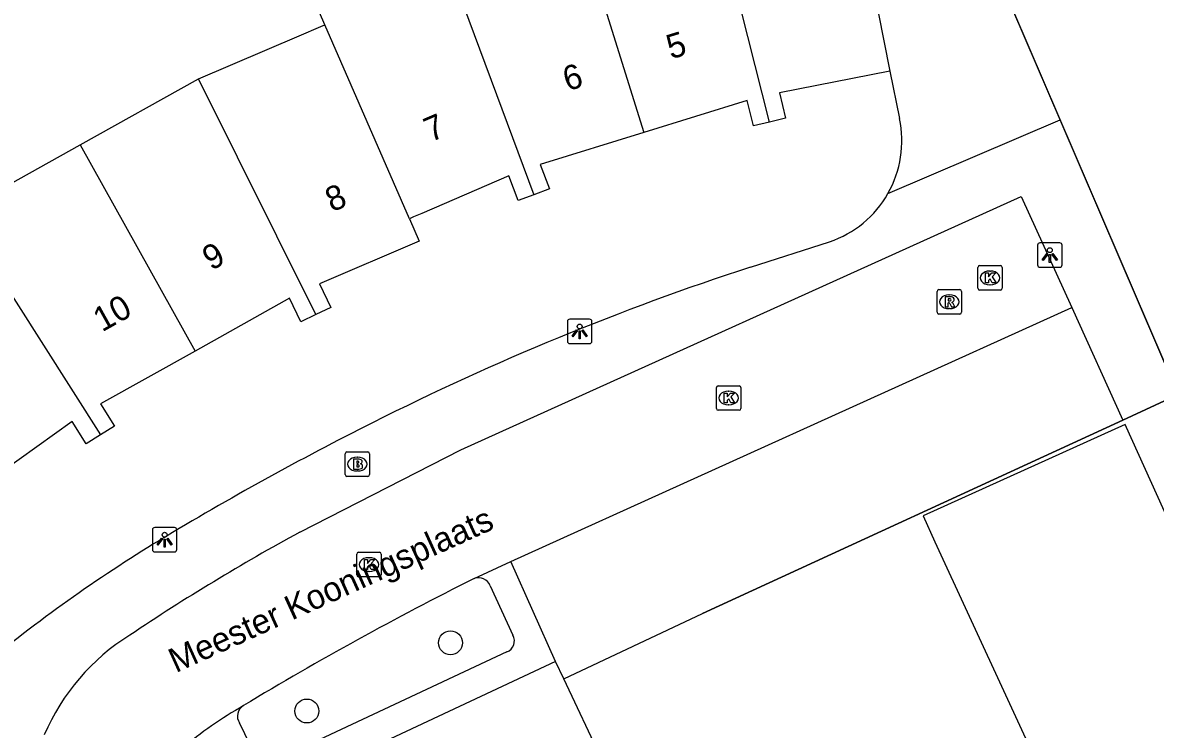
# Model space of a CAD drawing. Extents: x 160379 to 161131, y 383940 to 384849.
# Drawn here: x 160925.77 to 160972.04, y 384329.72 to 384358.59 of the extents above; entities that cross this region are included whole.
import ezdxf

# ---------------------------------------------------------------- set-up
doc = ezdxf.new("R2010")
doc.units = 0
for name, color, linetype in [('IMGEO_Boom', 7, 'Continuous'), ('IMGEO_Brandkraan', 7, 'Continuous'), ('IMGEO_Kolk', 7, 'Continuous'), ('IMGEO_Lichtpunt', 7, 'Continuous'), ('IMGEO_Muur', 7, 'Continuous'), ('IMGEO_Openbare_ruimte_label', 7, 'Continuous'), ('IMGEO_Pand', 7, 'Continuous'), ('IMGEO_Pand_nummerreeks', 7, 'Continuous'), ('IMGEO_Parkeervlak_open', 7, 'Continuous'), ('IMGEO_Rijbaan_lokaal_open', 7, 'Continuous'), ('IMGEO_Rioolput', 7, 'Continuous'), ('IMGEO_Voetpad_open', 7, 'Continuous')]:
    doc.layers.add(name, color=color, linetype=linetype)

msp = doc.modelspace()

# ---------------------------------------------------------------- linework, layer by layer
at = {"layer": 'IMGEO_Boom'}
for centre in [(160943.246, 384333.257), (160937.378, 384330.47)]:
    msp.add_circle(centre, 0.489, dxfattribs=at)
at = {"layer": 'IMGEO_Brandkraan'}
for p, q in [((160938.941, 384340.129), (160938.941, 384340.981)), ((160939.016, 384341.055), (160939.868, 384341.055)), ((160939.429, 384340.835), (160939.454, 384340.835)), ((160939.942, 384340.981), (160939.942, 384340.129)), ((160939.452, 384340.275), (160939.427, 384340.275)), ((160939.868, 384340.055), (160939.016, 384340.055))]:
    msp.add_line(p, q, dxfattribs=at)
for points in [[(160938.941, 384340.129), (160938.941, 384340.981)], [(160939.016, 384341.055), (160939.868, 384341.055)], [(160939.289, 384340.755), (160939.289, 384340.355), (160939.502, 384340.355)], [(160939.52, 384340.755), (160939.289, 384340.755)], [(160939.468, 384340.674), (160939.414, 384340.674), (160939.414, 384340.598)], [(160939.942, 384340.981), (160939.942, 384340.129)], [(160939.414, 384340.598), (160939.467, 384340.598)], [(160939.476, 384340.522), (160939.414, 384340.522), (160939.414, 384340.441)], [(160939.414, 384340.441), (160939.476, 384340.441)], [(160939.868, 384340.055), (160939.016, 384340.055)]]:
    msp.add_lwpolyline(points, dxfattribs=at)
for centre, radius, start, end in [((160939.018, 384340.979), 0.0765, 91.552, 178.448), ((160939.018, 384340.979), 0.0765, 91.552, 178.448), ((160939.469, 384340.636), 0.0379, 267.8285, 90.9355), ((160939.524, 384340.61), 0.145, 59.4692, 91.5367), ((160939.549, 384340.657), 0.0922, 285.5137, 58.1501), ((160939.866, 384340.979), 0.0765, 1.552, 88.448), ((160939.866, 384340.979), 0.0765, 1.552, 88.448), ((160939.477, 384340.481), 0.0404, 269.8759, 90.5077), ((160939.508, 384340.606), 0.251, 268.6676, 293.5347), ((160939.554, 384340.465), 0.105, 301.3115, 78.989), ((160939.018, 384340.131), 0.0765, 181.552, 268.448), ((160939.018, 384340.131), 0.0765, 181.552, 268.448), ((160939.866, 384340.131), 0.0765, 271.552, 358.448), ((160939.866, 384340.131), 0.0765, 271.552, 358.448)]:
    msp.add_arc(centre, radius, start, end, dxfattribs=at)
for centre, major_axis, ratio, start_param, end_param in [((160939.428, 384340.555), (-0.387, 0.002), 0.722429, 4.712389, 7.853982), ((160939.453, 384340.555), (-0.39, 0.002), 0.717154, 1.570796, 4.712389)]:
    msp.add_ellipse(centre, major_axis=major_axis, ratio=ratio, start_param=start_param, end_param=end_param, dxfattribs=at)
at = {"layer": 'IMGEO_Kolk'}
for p, q in [((160964.784, 384347.737), (160964.784, 384348.589)), ((160964.859, 384348.663), (160965.711, 384348.663)), ((160965.785, 384348.589), (160965.785, 384347.737)), ((160965.272, 384348.443), (160965.297, 384348.443)), ((160965.711, 384347.663), (160964.859, 384347.663)), ((160965.295, 384347.883), (160965.27, 384347.883)), ((160954.106, 384342.829), (160954.106, 384343.681)), ((160954.181, 384343.755), (160955.033, 384343.755)), ((160954.594, 384343.535), (160954.619, 384343.535)), ((160955.107, 384343.681), (160955.107, 384342.829)), ((160954.617, 384342.975), (160954.592, 384342.975)), ((160955.033, 384342.755), (160954.181, 384342.755)), ((160939.491, 384336.953), (160940.343, 384336.953)), ((160939.416, 384336.027), (160939.416, 384336.879)), ((160939.904, 384336.733), (160939.929, 384336.733)), ((160940.417, 384336.879), (160940.417, 384336.027)), ((160939.927, 384336.173), (160939.902, 384336.173)), ((160940.343, 384335.953), (160939.491, 384335.953))]:
    msp.add_line(p, q, dxfattribs=at)
for points in [[(160964.784, 384347.737), (160964.784, 384348.589)], [(160964.859, 384348.663), (160965.711, 384348.663)], [(160965.785, 384348.589), (160965.785, 384347.737)], [(160965.105, 384348.363), (160965.228, 384348.363), (160965.228, 384348.212), (160965.358, 384348.363), (160965.522, 384348.363), (160965.376, 384348.212), (160965.529, 384347.963), (160965.377, 384347.963), (160965.292, 384348.127), (160965.228, 384348.06), (160965.228, 384347.963), (160965.105, 384347.963), (160965.105, 384348.363)], [(160965.711, 384347.663), (160964.859, 384347.663)], [(160954.106, 384342.829), (160954.106, 384343.681)], [(160954.181, 384343.755), (160955.033, 384343.755)], [(160954.427, 384343.455), (160954.55, 384343.455), (160954.55, 384343.304), (160954.68, 384343.455), (160954.844, 384343.455), (160954.698, 384343.304), (160954.851, 384343.055), (160954.699, 384343.055), (160954.614, 384343.219), (160954.55, 384343.152), (160954.55, 384343.055), (160954.427, 384343.055), (160954.427, 384343.455)], [(160955.107, 384343.681), (160955.107, 384342.829)], [(160955.033, 384342.755), (160954.181, 384342.755)], [(160939.491, 384336.953), (160940.343, 384336.953)], [(160939.416, 384336.027), (160939.416, 384336.879)], [(160939.737, 384336.653), (160939.86, 384336.653), (160939.86, 384336.502), (160939.99, 384336.653), (160940.154, 384336.653), (160940.008, 384336.502), (160940.161, 384336.253), (160940.009, 384336.253), (160939.924, 384336.417), (160939.86, 384336.35), (160939.86, 384336.253), (160939.737, 384336.253), (160939.737, 384336.653)], [(160940.417, 384336.879), (160940.417, 384336.027)], [(160940.343, 384335.953), (160939.491, 384335.953)]]:
    msp.add_lwpolyline(points, dxfattribs=at)
for centre, start, end in [((160964.861, 384348.587), 91.552, 178.448), ((160964.861, 384348.587), 91.552, 178.448), ((160965.709, 384348.587), 1.552, 88.448), ((160965.709, 384348.587), 1.552, 88.448), ((160964.861, 384347.739), 181.552, 268.448), ((160964.861, 384347.739), 181.552, 268.448), ((160965.709, 384347.739), 271.552, 358.448), ((160965.709, 384347.739), 271.552, 358.448), ((160954.183, 384343.679), 91.552, 178.448), ((160954.183, 384343.679), 91.552, 178.448), ((160955.031, 384343.679), 1.552, 88.448), ((160955.031, 384343.679), 1.552, 88.448), ((160954.183, 384342.831), 181.552, 268.448), ((160954.183, 384342.831), 181.552, 268.448), ((160955.031, 384342.831), 271.552, 358.448), ((160955.031, 384342.831), 271.552, 358.448), ((160939.493, 384336.877), 91.552, 178.448), ((160939.493, 384336.877), 91.552, 178.448), ((160940.341, 384336.877), 1.552, 88.448), ((160940.341, 384336.877), 1.552, 88.448), ((160939.493, 384336.029), 181.552, 268.448), ((160939.493, 384336.029), 181.552, 268.448), ((160940.341, 384336.029), 271.552, 358.448), ((160940.341, 384336.029), 271.552, 358.448)]:
    msp.add_arc(centre, 0.0765, start, end, dxfattribs=at)
for centre, major_axis, ratio, start_param, end_param in [((160965.271, 384348.163), (-0.387, 0.002), 0.722429, 4.712389, 7.853982), ((160965.296, 384348.163), (-0.39, 0.002), 0.717154, 1.570796, 4.712389), ((160954.593, 384343.255), (-0.387, 0.002), 0.722429, 4.712389, 7.853982), ((160954.618, 384343.255), (-0.39, 0.002), 0.717154, 1.570796, 4.712389), ((160939.903, 384336.453), (-0.387, 0.002), 0.722429, 4.712389, 7.853982), ((160939.928, 384336.453), (-0.39, 0.002), 0.717154, 1.570796, 4.712389)]:
    msp.add_ellipse(centre, major_axis=major_axis, ratio=ratio, start_param=start_param, end_param=end_param, dxfattribs=at)
at = {"layer": 'IMGEO_Lichtpunt'}
for p, q in [((160967.228, 384349.5), (160967.228, 384348.693)), ((160967.228, 384349.5), (160967.228, 384348.693)), ((160968.13, 384349.595), (160967.322, 384349.595)), ((160968.13, 384349.595), (160967.322, 384349.595)), ((160968.224, 384348.693), (160968.224, 384349.5)), ((160968.224, 384348.693), (160968.224, 384349.5)), ((160967.322, 384348.599), (160968.13, 384348.599)), ((160967.322, 384348.599), (160968.13, 384348.599)), ((160948.024, 384346.38), (160948.024, 384345.573)), ((160948.024, 384346.38), (160948.024, 384345.573)), ((160948.926, 384346.475), (160948.118, 384346.475)), ((160948.926, 384346.475), (160948.118, 384346.475)), ((160949.02, 384345.573), (160949.02, 384346.38)), ((160949.02, 384345.573), (160949.02, 384346.38)), ((160948.118, 384345.479), (160948.926, 384345.479)), ((160948.118, 384345.479), (160948.926, 384345.479)), ((160931.071, 384337.872), (160931.071, 384337.065)), ((160931.071, 384337.872), (160931.071, 384337.065)), ((160931.973, 384337.967), (160931.165, 384337.967)), ((160931.973, 384337.967), (160931.165, 384337.967)), ((160932.067, 384337.065), (160932.067, 384337.872)), ((160932.067, 384337.065), (160932.067, 384337.872)), ((160931.165, 384336.971), (160931.973, 384336.971)), ((160931.165, 384336.971), (160931.973, 384336.971))]:
    msp.add_line(p, q, dxfattribs=at)
for points in [[(160967.602, 384349.164), (160967.641, 384349.136), (160967.453, 384348.874), (160967.415, 384348.901), (160967.602, 384349.164)], [(160967.704, 384349.116), (160967.751, 384349.116), (160967.751, 384348.794), (160967.704, 384348.794), (160967.704, 384349.116)], [(160967.814, 384349.136), (160967.852, 384349.163), (160968.039, 384348.901), (160968, 384348.873), (160967.814, 384349.136)], [(160948.398, 384346.044), (160948.437, 384346.016), (160948.249, 384345.754), (160948.211, 384345.781), (160948.398, 384346.044)], [(160948.5, 384345.996), (160948.547, 384345.996), (160948.547, 384345.674), (160948.5, 384345.674), (160948.5, 384345.996)], [(160948.61, 384346.016), (160948.648, 384346.043), (160948.835, 384345.781), (160948.796, 384345.753), (160948.61, 384346.016)], [(160931.445, 384337.536), (160931.484, 384337.508), (160931.296, 384337.246), (160931.258, 384337.273), (160931.445, 384337.536)], [(160931.547, 384337.488), (160931.594, 384337.488), (160931.594, 384337.166), (160931.547, 384337.166), (160931.547, 384337.488)], [(160931.657, 384337.508), (160931.695, 384337.535), (160931.882, 384337.273), (160931.843, 384337.245), (160931.657, 384337.508)]]:
    msp.add_lwpolyline(points, dxfattribs=at)
for centre in [(160967.727, 384349.298), (160948.523, 384346.178), (160931.57, 384337.67)]:
    msp.add_circle(centre, 0.0994, dxfattribs=at)
for centre, start, end in [((160967.322, 384349.5), 90, 180), ((160967.322, 384349.5), 90, 180), ((160968.13, 384349.5), 0, 90), ((160968.13, 384349.5), 0, 90), ((160967.322, 384348.693), 180, 270), ((160967.322, 384348.693), 180, 270), ((160968.13, 384348.693), 270, 0), ((160968.13, 384348.693), 270, 360), ((160948.118, 384346.38), 90, 180), ((160948.118, 384346.38), 90, 180), ((160948.926, 384346.38), 0, 90), ((160948.926, 384346.38), 0, 90), ((160948.118, 384345.573), 180, 270), ((160948.118, 384345.573), 180, 270), ((160948.926, 384345.573), 270, 0), ((160948.926, 384345.573), 270, 360), ((160931.165, 384337.872), 90, 180), ((160931.165, 384337.872), 90, 180), ((160931.973, 384337.872), 0, 90), ((160931.973, 384337.872), 0, 90), ((160931.165, 384337.065), 180, 270), ((160931.165, 384337.065), 180, 270), ((160931.973, 384337.065), 270, 0), ((160931.973, 384337.065), 270, 360)]:
    msp.add_arc(centre, 0.0946, start, end, dxfattribs=at)
at = {"layer": 'IMGEO_Muur'}
for points in [[(160966.362, 384365.747), (160963.821, 384364.69), (160972.964, 384343.393), (160970.707, 384342.354)], [(160970.707, 384342.354), (160953.539, 384334.451)]]:
    msp.add_lwpolyline(points, dxfattribs=at)
at = {"layer": 'IMGEO_Pand'}
for points in [[(160959.33, 384366.063), (160961.195, 384356.614)], [(160956.276, 384354.529), (160953.64, 384364.983)], [(160948.274, 384363.311), (160951.142, 384354.106)], [(160938.117, 384358.498), (160937.718, 384359.412), (160942.908, 384361.638)], [(160942.908, 384361.638), (160946.644, 384351.561)], [(160932.947, 384356.289), (160937.061, 384358.047), (160937.954, 384358.429), (160938.117, 384358.498)], [(160941.572, 384350.582), (160938.117, 384358.498)], [(160961.195, 384356.614), (160956.68, 384355.728), (160956.932, 384354.688), (160956.276, 384354.529)], [(160928.121, 384353.598), (160932.947, 384356.289)], [(160937.745, 384346.662), (160932.947, 384356.289)], [(160956.276, 384354.529), (160955.621, 384354.371), (160955.37, 384355.411), (160951.142, 384354.106)], [(160951.142, 384354.106), (160946.913, 384352.801), (160947.284, 384351.797), (160946.644, 384351.561)], [(160923.164, 384350.833), (160928.121, 384353.598)], [(160928.121, 384353.598), (160932.81, 384345.172)], [(160946.644, 384351.561), (160946.004, 384351.325), (160945.634, 384352.328), (160942.077, 384350.799), (160941.735, 384350.652), (160941.572, 384350.582)], [(160923.164, 384350.833), (160928.95, 384341.753)], [(160941.572, 384350.582), (160941.972, 384349.665), (160937.893, 384347.922), (160938.359, 384346.959), (160937.745, 384346.662)], [(160937.745, 384346.662), (160937.132, 384346.365), (160936.666, 384347.328), (160932.81, 384345.172)], [(160932.81, 384345.172), (160928.954, 384343.015), (160929.519, 384342.106), (160928.95, 384341.753)], [(160928.95, 384341.753), (160928.359, 384341.386), (160927.795, 384342.295), (160924.167, 384339.712), (160923.589, 384340.534)], [(160986.764, 384323.863), (160984.723, 384328.376), (160978.345, 384325.492), (160970.86, 384342.047), (160970.802, 384342.176), (160962.547, 384338.444), (160963.028, 384337.381), (160967.394, 384327.922)], [(160947.54, 384332.492), (160933.153, 384325.75), (160934.769, 384322.306)], [(160947.872, 384331.78), (160947.54, 384332.492)], [(160945.998, 384322.759), (160945.93, 384322.902), (160944.422, 384326.089), (160949.445, 384328.465), (160947.872, 384331.78)]]:
    msp.add_lwpolyline(points, dxfattribs=at)
at = {"layer": 'IMGEO_Parkeervlak_open'}
msp.add_lwpolyline([(160947.872, 384331.78), (160953.539, 384334.451), (160970.707, 384342.354)], dxfattribs=at)
at = {"layer": 'IMGEO_Rijbaan_lokaal_open'}
for points in [[(160937.094, 384337.778), (160943.664, 384341.144), (160966.551, 384351.49), (160968.629, 384346.954)], [(160945.717, 384336.577), (160968.629, 384346.954)], [(160944.215, 384335.883), (160945.717, 384336.577)]]:
    msp.add_lwpolyline(points, dxfattribs=at)
for centre, radius, start, end in [((160980.368, 384258.522), 90.301, 118.63477, 123.78887), ((161004.521, 384215.29), 134.831, 116.56875, 121.14334), ((160934.911, 384325.947), 8.989, 121.9944, 156.7637), ((160943.156, 384316.018), 16.889, 119.6957, 130.1356)]:
    msp.add_arc(centre, radius, start, end, dxfattribs=at)
at = {"layer": 'IMGEO_Rioolput'}
for p, q in [((160963.119, 384346.76), (160963.119, 384347.612)), ((160963.194, 384347.686), (160964.046, 384347.686)), ((160964.12, 384347.612), (160964.12, 384346.76)), ((160963.607, 384347.466), (160963.632, 384347.466)), ((160964.046, 384346.686), (160963.194, 384346.686)), ((160963.63, 384346.906), (160963.605, 384346.906))]:
    msp.add_line(p, q, dxfattribs=at)
for points in [[(160963.119, 384346.76), (160963.119, 384347.612)], [(160963.194, 384347.686), (160964.046, 384347.686)], [(160964.12, 384347.612), (160964.12, 384346.76)], [(160963.708, 384347.384), (160963.456, 384347.386), (160963.456, 384346.986)], [(160963.456, 384346.986), (160963.58, 384346.986), (160963.58, 384347.148), (160963.591, 384347.148)], [(160963.634, 384347.305), (160963.58, 384347.305), (160963.58, 384347.224)], [(160963.58, 384347.224), (160963.632, 384347.224)], [(160963.638, 384347.119), (160963.709, 384346.986), (160963.849, 384346.986), (160963.784, 384347.112)], [(160964.046, 384346.686), (160963.194, 384346.686)]]:
    msp.add_lwpolyline(points, dxfattribs=at)
for centre, radius, start, end in [((160963.196, 384347.61), 0.0765, 91.552, 178.448), ((160963.196, 384347.61), 0.0765, 91.552, 178.448), ((160964.044, 384347.61), 0.0765, 1.552, 88.448), ((160964.044, 384347.61), 0.0765, 1.552, 88.448), ((160963.59, 384347.095), 0.0533, 26.0293, 88.6989), ((160963.616, 384347.413), 0.19, 274.7715, 282.9687), ((160963.64, 384347.209), 0.0964, 77.0061, 93.1865), ((160963.654, 384347.266), 0.0378, 276.6634, 79.6772), ((160963.707, 384347.274), 0.109, 350.3612, 89.416), ((160963.705, 384347.274), 0.112, 277.5842, 350.9817), ((160963.689, 384347.059), 0.108, 29.5134, 73.7905), ((160963.196, 384346.762), 0.0765, 181.552, 268.448), ((160963.196, 384346.762), 0.0765, 181.552, 268.448), ((160964.044, 384346.762), 0.0765, 271.552, 358.448), ((160964.044, 384346.762), 0.0765, 271.552, 358.448)]:
    msp.add_arc(centre, radius, start, end, dxfattribs=at)
for centre, major_axis, ratio, start_param, end_param in [((160963.606, 384347.186), (-0.387, 0.002), 0.722429, 4.712389, 7.853982), ((160963.631, 384347.186), (-0.39, 0.002), 0.717154, 1.570796, 4.712389)]:
    msp.add_ellipse(centre, major_axis=major_axis, ratio=ratio, start_param=start_param, end_param=end_param, dxfattribs=at)
at = {"layer": 'IMGEO_Voetpad_open'}
for points in [[(160968.142, 384354.625), (160963.821, 384364.69), (160966.362, 384365.747)], [(160961.195, 384356.614), (160961.584, 384354.67)], [(160961.116, 384351.609), (160968.142, 384354.625)], [(160970.707, 384342.354), (160972.964, 384343.393), (160968.142, 384354.625)], [(160955.502, 384348.606), (160958.73, 384349.634)], [(160968.629, 384346.954), (160970.707, 384342.354)], [(160947.54, 384332.492), (160945.717, 384336.577)], [(160944.867, 384335.59), (160945.787, 384333.565)], [(160945.548, 384332.885), (160935.936, 384328.385)], [(160935.275, 384328.634), (160934.63, 384329.983)]]:
    msp.add_lwpolyline(points, dxfattribs=at)
for centre, radius, start, end in [((160957.324, 384353.755), 4.357, 330.4942, 12.1204), ((160957.332, 384353.751), 4.348, 288.7514, 330.4807), ((160989.673, 384243.736), 110.297, 108.04782, 116.72888), ((160997.608, 384227.711), 128.179, 116.67506, 121.12072), ((160964.285, 384283.453), 63.237, 121.37691, 129.51133), ((160944.388, 384335.395), 0.518, 22.1281, 109.4749), ((160945.393, 384333.321), 0.463, 289.5546, 31.7153), ((160935.038, 384330.262), 0.495, 120.2798, 214.3363)]:
    msp.add_arc(centre, radius, start, end, dxfattribs=at)

# ---------------------------------------------------------------- texts
at = {"layer": 'IMGEO_Openbare_ruimte_label'}
msp.add_text('Meester Kooningsplaats', height=1, rotation=24.3871, dxfattribs=at).set_placement((160932.025, 384332.015))
at = {"layer": 'IMGEO_Pand_nummerreeks'}
for s, rotation, p in [('5', 17.1532, (160952.25, 384357.085)), ('6', 17.1486, (160948.021, 384355.781)), ('7', 23.2621, (160942.436, 384353.696)), ('8', 23.136, (160938.404, 384350.838)), ('9', 29.2108, (160933.475, 384348.44)), ('10', 29.2221, (160929.013, 384345.934))]:
    msp.add_text(s, height=1, rotation=rotation, dxfattribs=at).set_placement(p)

doc.saveas('drawing.dxf')
